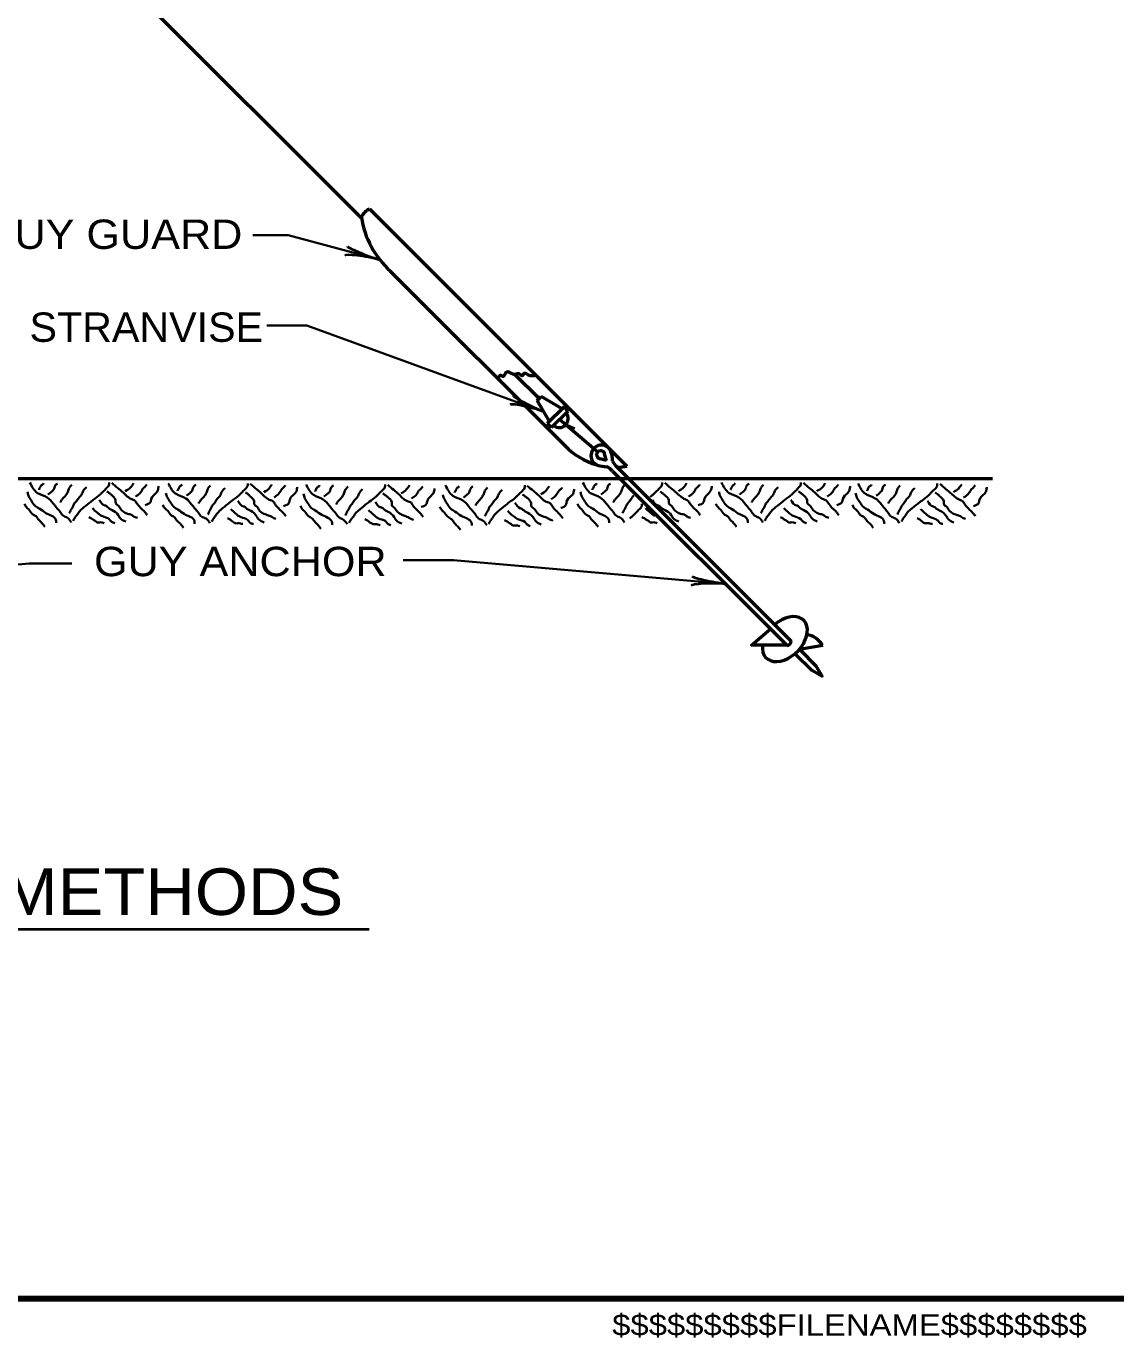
# Model space of a CAD drawing. Extents: x -34 to 821, y -14 to 530.
# Drawn here: x 481.5 to 593.8, y -6.2 to 128.9 of the extents above; entities that cross this region are included whole.
import ezdxf
from ezdxf.enums import TextEntityAlignment as Align

# ---------------------------------------------------------------- set-up
doc = ezdxf.new("R2010")
doc.units = 0
doc.header["$LTSCALE"] = 1.2
doc.layers.add('1', color=7, linetype='Continuous', lineweight=53)

msp = doc.modelspace()

# ---------------------------------------------------------------- linework, layer by layer
at = {"layer": '1'}
for p, q in [((462.551, 162.594), (516.047, 109.122)), ((516.887, 110.082), (543.407, 83.562)), ((519.023, 103.674), (536.999, 85.698)), ((531.791, 93.09), (534.359, 90.546)), ((534.143, 90.33), (534.575, 90.738)), ((536.711, 89.466), (534.575, 90.738)), ((535.415, 88.17), (534.143, 90.33)), ((536.927, 89.682), (535.199, 87.978)), ((537.335, 89.25), (535.631, 87.546)), ((537.335, 89.25), (536.927, 89.682)), ((535.631, 87.546), (535.199, 87.978)), ((540.407, 85.026), (536.447, 88.362)), ((537.095, 87.834), (537.983, 87.402)), ((541.295, 84.138), (540.599, 84.33)), ((541.295, 84.138), (541.103, 84.834)), ((542.351, 83.514), (560.327, 65.538)), ((355.079, 82.29), (581.063, 82.29)), ((561.191, 64.698), (563.567, 65.106)), ((561.191, 64.698), (562.895, 62.97))]:
    msp.add_line(p, q, dxfattribs=at)
at = {"layer": '1', "lineweight": 35}
for p, q in [((508.511, 107.37), (504.863, 107.37)), ((517.847, 104.85), (508.511, 107.37)), ((510.407, 98.058), (506.303, 98.058)), ((534.815, 89.178), (510.407, 98.058)), ((481.823, 73.53), (461.831, 71.778)), ((481.823, 73.53), (486.215, 73.53)), ((525.527, 73.89), (520.343, 73.89)), ((525.527, 73.89), (553.535, 71.442))]:
    msp.add_line(p, q, dxfattribs=at)
at = {"layer": '1', "lineweight": 40}
msp.add_line((426.765, 35.847), (516.827, 35.847), dxfattribs=at)
at = {"layer": '1', "lineweight": 158}
msp.add_line((814.88, -2.224), (23.28, -2.224), dxfattribs=at)
at = {"layer": '1'}
for points in [[(541.919, 83.058), (559.871, 65.106), (556.247, 65.106), (558.167, 66.786)], [(560.735, 64.242), (562.439, 62.538), (563.519, 61.914), (562.895, 62.97)]]:
    msp.add_lwpolyline(points, dxfattribs=at)
for centre, radius, start, end in [((517.718, 108.403), 1.872, 116.15616, 153.84384), ((525.291, 110.626), 9.358, 188.58388, 228.01714), ((536.43, 88.454), 0.911, 230.20411, 39.79589), ((542.156, 90.508), 7.05, 222.90975, 254.56822), ((540.763, 84.67), 1.073, 22.37581, 247.62419), ((540.7, 84.731), 0.423, 13.9871, 256.0129), ((539.132, 84.15), 2.783, 358.69833, 19.49446), ((543.511, 84.865), 1.777, 205.99574, 229.75423), ((541.398, 86.842), 3.332, 251.74116, 268.96028), ((540.559, 81.914), 1.777, 40.24577, 64.00426), ((542.156, 90.508), 7.05, 272.0576, 280.22035), ((561.432, 63.756), 2.526, 32.48706, 78.42981), ((559.86, 65.564), 0.464, 272.04039, 357.95961)]:
    msp.add_arc(centre, radius, start, end, dxfattribs=at)
at = {"layer": '1', "lineweight": 40}
for centre, major_axis, ratio, start_param, end_param in [((516.604, 105.456), (1.997, -0.755), 0.07063, 3.1407148, 5.41811), ((516.486, 104.877), (2.135, -0.377), 0.122415, 0.8963533, 3.1415927), ((533.634, 89.885), (-1.924, 0.926), 0.07063, 6.2823074, 8.5597026), ((533.634, 89.885), (-1.924, 0.926), 0.07063, 6.2823074, 8.5597026), ((533.465, 89.318), (2.094, -0.561), 0.122415, 0.8963533, 3.1415927), ((533.465, 89.318), (2.094, -0.561), 0.122415, 0.8963533, 3.1415927), ((552.207, 71.815), (2.098, -0.397), 0.07063, 3.1407148, 5.41811), ((552.191, 71.224), (2.168, 0), 0.122415, 0.8963533, 3.1415927)]:
    msp.add_ellipse(centre, major_axis=major_axis, ratio=ratio, start_param=start_param, end_param=end_param, dxfattribs=at)
at = {"layer": '1'}
msp.add_ellipse((559.673, 65.751), major_axis=(-1.934, -1.934), ratio=0.663245, start_param=5.5824837, end_param=10.8796755, dxfattribs=at)
msp.add_spline([(530.159, 92.562), (530.423, 92.946), (530.591, 92.826), (530.903, 93.138), (531.095, 93.306), (531.479, 93.138), (532.007, 93.066), (532.247, 93.114), (532.631, 92.898), (532.823, 93.138), (533.231, 92.994), (533.591, 92.898), (533.999, 92.97)], degree=3, dxfattribs=at)
at = {"layer": '1', "lineweight": 35}
for points in [[(481.895, 81.882), (482.663, 80.802), (483.671, 80.346), (484.295, 79.722), (484.607, 79.338), (484.991, 78.858), (485.303, 78.474), (485.759, 78.258), (486.143, 77.778)], [(483.287, 81.81), (483.167, 81.642), (483.119, 81.642), (483.047, 81.57), (482.855, 81.21), (482.831, 81.138)], [(484.727, 81.762), (484.487, 81.57), (484.415, 81.378), (484.319, 81.138), (484.175, 80.994), (484.103, 80.922), (483.743, 80.634)], [(486.215, 81.642), (485.999, 81.402), (485.831, 81.018), (485.639, 80.634), (485.231, 80.178), (485.063, 79.938), (484.991, 79.818)], [(487.727, 81.402), (487.391, 81.018), (487.199, 80.61), (486.887, 80.25), (486.647, 79.914), (486.407, 79.626), (486.311, 79.362), (486.143, 79.098), (485.951, 78.714)], [(490.055, 81.882), (490.055, 81.738), (489.983, 81.498), (489.815, 81.354), (489.671, 81.186), (489.359, 80.874), (489.119, 80.658), (488.423, 80.106), (488.039, 79.794), (487.271, 79.17), (486.959, 78.858), (486.815, 78.642), (486.575, 78.33), (486.335, 77.946)], [(490.319, 81.858), (490.943, 81.306), (491.495, 80.85), (492.407, 80.154), (492.647, 80.058), (492.887, 79.77), (493.271, 79.29), (493.727, 78.834), (493.967, 78.522)], [(491.711, 80.994), (492.263, 81.378), (492.383, 81.522), (492.575, 81.81)], [(492.767, 80.442), (493.199, 80.754), (493.463, 81.138), (493.535, 81.258), (493.703, 81.402), (493.919, 81.69)], [(493.775, 79.554), (494.303, 79.866), (494.399, 80.202), (494.903, 80.826), (495.047, 81.018), (495.119, 81.33), (495.167, 81.498)], [(496.151, 81.786), (496.943, 80.706), (497.951, 80.25), (498.551, 79.626), (498.863, 79.242), (499.247, 78.762), (499.559, 78.378), (500.039, 78.162), (500.423, 77.682)], [(497.567, 81.69), (497.447, 81.546), (497.399, 81.546), (497.327, 81.474), (497.135, 81.114), (497.087, 81.042)], [(498.983, 81.666), (498.767, 81.474), (498.671, 81.282), (498.599, 81.042), (498.455, 80.898), (498.359, 80.802), (498.023, 80.538)], [(500.495, 81.546), (500.255, 81.306), (500.111, 80.922), (499.919, 80.538), (499.487, 80.082), (499.343, 79.842), (499.247, 79.722)], [(502.007, 81.306), (501.647, 80.922), (501.455, 80.49), (501.143, 80.154), (500.927, 79.794), (500.687, 79.53), (500.567, 79.266), (500.423, 79.002), (500.231, 78.594)], [(504.335, 81.786), (504.335, 81.642), (504.239, 81.402), (504.095, 81.234), (503.951, 81.09), (503.639, 80.778), (503.399, 80.538), (502.703, 80.01), (502.319, 79.698), (501.551, 79.074), (501.239, 78.762), (501.071, 78.546), (500.855, 78.234), (500.615, 77.85)], [(504.599, 81.738), (505.223, 81.21), (505.751, 80.754), (506.687, 80.058), (506.927, 79.962), (507.143, 79.65), (507.527, 79.194), (508.007, 78.738), (508.247, 78.426)], [(505.991, 80.898), (506.543, 81.282), (506.639, 81.426), (506.831, 81.69)], [(507.047, 80.346), (507.455, 80.658), (507.743, 81.042), (507.815, 81.162), (507.959, 81.306), (508.199, 81.594)], [(508.031, 79.458), (508.583, 79.77), (508.655, 80.106), (509.159, 80.73), (509.327, 80.922), (509.399, 81.234), (509.423, 81.402)], [(510.335, 81.69), (511.103, 80.61), (512.111, 80.13), (512.735, 79.53), (513.047, 79.122), (513.431, 78.666), (513.743, 78.282), (514.199, 78.042), (514.583, 77.586)], [(511.727, 81.594), (511.607, 81.45), (511.583, 81.45), (511.487, 81.378), (511.295, 81.018), (511.271, 80.946)], [(513.167, 81.57), (512.927, 81.378), (512.855, 81.186), (512.783, 80.946), (512.615, 80.778), (512.543, 80.706), (512.183, 80.442)], [(514.679, 81.45), (514.439, 81.21), (514.271, 80.826), (514.079, 80.442), (513.671, 79.986), (513.503, 79.746), (513.431, 79.626)], [(516.167, 81.21), (515.831, 80.826), (515.639, 80.394), (515.327, 80.058), (515.087, 79.698), (514.871, 79.434), (514.751, 79.17), (514.583, 78.882), (514.391, 78.498)], [(518.495, 81.69), (518.495, 81.522), (518.423, 81.306), (518.255, 81.138), (518.111, 80.994), (517.799, 80.682), (517.559, 80.442), (516.863, 79.914), (516.479, 79.602), (515.711, 78.978), (515.399, 78.666), (515.255, 78.426), (515.015, 78.138), (514.775, 77.73)], [(518.759, 81.642), (519.383, 81.114), (519.935, 80.634), (520.847, 79.938), (521.087, 79.866), (521.327, 79.554), (521.711, 79.098), (522.167, 78.642), (522.407, 78.33)], [(520.151, 80.778), (520.703, 81.186), (520.823, 81.33), (521.015, 81.594)], [(521.207, 80.25), (521.639, 80.562), (521.903, 80.946), (521.975, 81.066), (522.143, 81.21), (522.359, 81.474)], [(522.215, 79.362), (522.743, 79.674), (522.839, 80.01), (523.343, 80.634), (523.487, 80.826), (523.559, 81.138), (523.607, 81.282)], [(524.711, 81.594), (525.479, 80.514), (526.487, 80.034), (527.111, 79.41), (527.423, 79.026), (527.807, 78.57), (528.119, 78.186), (528.575, 77.946), (528.959, 77.49)], [(526.103, 81.498), (525.983, 81.354), (525.935, 81.354), (525.863, 81.258), (525.671, 80.922), (525.623, 80.85)], [(527.519, 81.474), (527.303, 81.258), (527.231, 81.066), (527.135, 80.85), (526.991, 80.682), (526.919, 80.61), (526.559, 80.346)], [(529.031, 81.354), (528.815, 81.114), (528.647, 80.73), (528.455, 80.346), (528.023, 79.866), (527.879, 79.65), (527.807, 79.53)], [(530.543, 81.114), (530.207, 80.73), (530.015, 80.298), (529.703, 79.962), (529.463, 79.602), (529.223, 79.338), (529.127, 79.074), (528.959, 78.786), (528.767, 78.402)], [(532.871, 81.594), (532.871, 81.426), (532.799, 81.21), (532.631, 81.042), (532.487, 80.898), (532.175, 80.586), (531.935, 80.346), (531.239, 79.818), (530.855, 79.506), (530.087, 78.882), (529.775, 78.57), (529.607, 78.33), (529.391, 78.018), (529.151, 77.634)], [(533.135, 81.546), (533.759, 81.018), (534.311, 80.538), (535.223, 79.842), (535.463, 79.77), (535.703, 79.458), (536.087, 79.002), (536.543, 78.522), (536.783, 78.21)], [(534.527, 80.682), (535.079, 81.066), (535.199, 81.234), (535.391, 81.498)], [(535.583, 80.154), (536.015, 80.466), (536.279, 80.85), (536.351, 80.97), (536.495, 81.114), (536.735, 81.378)], [(536.591, 79.266), (537.119, 79.578), (537.191, 79.914), (537.695, 80.538), (537.863, 80.73), (537.935, 81.042), (537.983, 81.186)], [(538.871, 81.882), (539.639, 80.802), (540.647, 80.346), (541.271, 79.722), (541.583, 79.338), (541.967, 78.858), (542.279, 78.474), (542.735, 78.258), (543.143, 77.778)], [(540.263, 81.81), (540.143, 81.642), (540.119, 81.642), (540.047, 81.57), (539.855, 81.21), (539.807, 81.138)], [(541.703, 81.762), (541.463, 81.57), (541.391, 81.378), (541.319, 81.138), (541.151, 80.994), (541.079, 80.922), (540.743, 80.634)], [(543.215, 81.642), (542.975, 81.402), (542.831, 81.018), (542.639, 80.634), (542.207, 80.178), (542.039, 79.938), (541.967, 79.818)], [(547.031, 81.882), (547.031, 81.738), (546.959, 81.498), (546.815, 81.354), (546.647, 81.186), (546.335, 80.874), (546.119, 80.658), (545.807, 80.418)], [(547.319, 81.858), (547.919, 81.306), (548.471, 80.85), (549.407, 80.154), (549.623, 80.058), (549.863, 79.77), (550.247, 79.29), (550.727, 78.834), (550.943, 78.522)], [(548.711, 80.994), (549.239, 81.378), (549.359, 81.522), (549.551, 81.81)], [(549.743, 80.442), (550.175, 80.754), (550.439, 81.138), (550.511, 81.258), (550.679, 81.402), (550.919, 81.69)], [(550.751, 79.554), (551.303, 79.866), (551.375, 80.202), (551.879, 80.826), (552.023, 81.018), (552.119, 81.33), (552.143, 81.498)], [(553.151, 81.882), (553.919, 80.802), (554.927, 80.346), (555.551, 79.722), (555.863, 79.338), (556.247, 78.858), (556.559, 78.474), (557.015, 78.258), (557.399, 77.778)], [(554.543, 81.81), (554.423, 81.642), (554.375, 81.642), (554.303, 81.57), (554.111, 81.21), (554.087, 81.138)], [(555.983, 81.762), (555.743, 81.57), (555.671, 81.378), (555.575, 81.138), (555.431, 80.994), (555.359, 80.922), (554.999, 80.634)], [(557.471, 81.642), (557.255, 81.402), (557.087, 81.018), (556.895, 80.634), (556.463, 80.178), (556.319, 79.938), (556.247, 79.818)], [(558.983, 81.402), (558.647, 81.018), (558.455, 80.61), (558.143, 80.25), (557.903, 79.914), (557.663, 79.626), (557.567, 79.362), (557.399, 79.098), (557.207, 78.714)], [(561.311, 81.882), (561.311, 81.738), (561.239, 81.498), (561.071, 81.354), (560.927, 81.186), (560.615, 80.874), (560.375, 80.658), (559.679, 80.106), (559.295, 79.794), (558.527, 79.17), (558.215, 78.858), (558.071, 78.642), (557.831, 78.33), (557.591, 77.946)], [(561.575, 81.858), (562.199, 81.306), (562.751, 80.85), (563.663, 80.154), (563.903, 80.058), (564.143, 79.77), (564.527, 79.29), (564.983, 78.834), (565.223, 78.522)], [(562.967, 80.994), (563.519, 81.378), (563.639, 81.522), (563.831, 81.81)], [(564.023, 80.442), (564.455, 80.754), (564.719, 81.138), (564.791, 81.258), (564.959, 81.402), (565.175, 81.69)], [(565.031, 79.554), (565.559, 79.866), (565.655, 80.202), (566.159, 80.826), (566.303, 81.018), (566.375, 81.33), (566.423, 81.498)], [(567.215, 81.786), (567.983, 80.706), (568.991, 80.25), (569.615, 79.626), (569.927, 79.242), (570.311, 78.762), (570.623, 78.378), (571.079, 78.162), (571.463, 77.682)], [(568.607, 81.69), (568.487, 81.546), (568.463, 81.546), (568.367, 81.474), (568.175, 81.114), (568.151, 81.042)], [(570.047, 81.666), (569.807, 81.474), (569.735, 81.282), (569.663, 81.042), (569.495, 80.898), (569.423, 80.802), (569.087, 80.538)], [(571.559, 81.546), (571.319, 81.306), (571.175, 80.922), (570.983, 80.538), (570.551, 80.082), (570.383, 79.842), (570.311, 79.722)], [(573.071, 81.306), (572.711, 80.922), (572.519, 80.49), (572.207, 80.154), (571.967, 79.794), (571.751, 79.53), (571.631, 79.266), (571.463, 79.002), (571.271, 78.594)], [(575.375, 81.786), (575.375, 81.642), (575.303, 81.402), (575.159, 81.234), (574.991, 81.09), (574.679, 80.778), (574.463, 80.538), (573.767, 80.01), (573.359, 79.698), (572.591, 79.074), (572.279, 78.762), (572.135, 78.546), (571.895, 78.234), (571.679, 77.85)], [(575.663, 81.738), (576.263, 81.21), (576.815, 80.754), (577.751, 80.058), (577.967, 79.962), (578.207, 79.65), (578.591, 79.194), (579.047, 78.738), (579.287, 78.426)], [(577.055, 80.898), (577.583, 81.282), (577.703, 81.426), (577.895, 81.69)], [(578.087, 80.346), (578.519, 80.658), (578.783, 81.042), (578.855, 81.162), (579.023, 81.306), (579.263, 81.594)], [(579.095, 79.458), (579.647, 79.77), (579.719, 80.106), (580.223, 80.73), (580.367, 80.922), (580.463, 81.234), (580.487, 81.402)], [(481.631, 80.922), (481.775, 80.442), (482.087, 79.938), (482.471, 79.434), (482.855, 79.218), (483.527, 78.738), (484.559, 78.042), (484.607, 77.73)], [(489.047, 80.106), (489.623, 79.506), (489.743, 79.482), (489.863, 79.362), (490.367, 79.05), (490.991, 78.522), (491.183, 78.21), (491.759, 77.85)], [(489.815, 80.946), (490.055, 80.802), (490.295, 80.61), (490.703, 80.058), (490.751, 79.722), (491.063, 79.434), (491.183, 79.242), (491.951, 78.666), (492.407, 78.522), (492.527, 78.426), (492.959, 78.234)], [(495.887, 80.802), (496.055, 80.346), (496.367, 79.842), (496.751, 79.338), (497.135, 79.098), (497.783, 78.642), (498.839, 77.946), (498.863, 77.634)], [(503.327, 79.986), (503.903, 79.41), (504.023, 79.386), (504.143, 79.266), (504.647, 78.954), (505.247, 78.402), (505.439, 78.114), (506.039, 77.754)], [(504.095, 80.85), (504.335, 80.706), (504.551, 80.49), (504.983, 79.962), (505.031, 79.602), (505.343, 79.338), (505.439, 79.146), (506.231, 78.57), (506.687, 78.402), (506.807, 78.33), (507.239, 78.138)], [(510.071, 80.706), (510.215, 80.25), (510.527, 79.746), (510.911, 79.242), (511.295, 79.002), (511.967, 78.546), (512.999, 77.85), (513.047, 77.538)], [(517.487, 79.89), (518.063, 79.314), (518.183, 79.29), (518.303, 79.17), (518.807, 78.858), (519.431, 78.306), (519.623, 77.994), (520.199, 77.658)], [(518.255, 80.754), (518.495, 80.586), (518.735, 80.394), (519.167, 79.866), (519.191, 79.506), (519.503, 79.242), (519.623, 79.05), (520.391, 78.474), (520.847, 78.306), (520.967, 78.234), (521.399, 78.042)], [(524.423, 80.61), (524.591, 80.154), (524.903, 79.65), (525.287, 79.146), (525.671, 78.906), (526.319, 78.45), (527.375, 77.754), (527.423, 77.442)], [(531.863, 79.794), (532.439, 79.218), (532.559, 79.17), (532.679, 79.074), (533.183, 78.762), (533.807, 78.21), (533.999, 77.898), (534.575, 77.562)], [(532.631, 80.658), (532.871, 80.49), (533.111, 80.298), (533.519, 79.77), (533.567, 79.41), (533.879, 79.146), (533.999, 78.954), (534.767, 78.378), (535.223, 78.21), (535.343, 78.138), (535.775, 77.946)], [(538.607, 80.922), (538.751, 80.442), (539.063, 79.938), (539.447, 79.434), (539.855, 79.218), (540.503, 78.738), (541.535, 78.042), (541.583, 77.73)], [(544.127, 80.538), (543.863, 80.25), (543.647, 79.914), (543.407, 79.626), (543.287, 79.362), (543.143, 79.098), (542.927, 78.714)], [(546.023, 80.106), (546.623, 79.506), (546.719, 79.482), (546.839, 79.362), (547.343, 79.05), (547.967, 78.522), (548.159, 78.21), (548.735, 77.85)], [(546.815, 80.946), (547.031, 80.802), (547.271, 80.61), (547.703, 80.058), (547.727, 79.722), (548.039, 79.434), (548.159, 79.242), (548.927, 78.666), (549.407, 78.522), (549.527, 78.426), (549.935, 78.234)], [(552.887, 80.922), (553.031, 80.442), (553.343, 79.938), (553.727, 79.434), (554.111, 79.218), (554.783, 78.738), (555.815, 78.042), (555.863, 77.73)], [(560.303, 80.106), (560.879, 79.506), (560.999, 79.482), (561.119, 79.362), (561.623, 79.05), (562.247, 78.522), (562.439, 78.21), (563.015, 77.85)], [(561.071, 80.946), (561.311, 80.802), (561.551, 80.61), (561.959, 80.058), (562.007, 79.722), (562.319, 79.434), (562.439, 79.242), (563.207, 78.666), (563.663, 78.522), (563.783, 78.426), (564.215, 78.234)], [(566.951, 80.802), (567.095, 80.346), (567.407, 79.842), (567.791, 79.338), (568.175, 79.098), (568.847, 78.642), (569.879, 77.946), (569.927, 77.634)], [(574.367, 79.986), (574.967, 79.41), (575.063, 79.386), (575.183, 79.266), (575.687, 78.954), (576.311, 78.402), (576.503, 78.114), (577.079, 77.754)], [(575.159, 80.85), (575.375, 80.706), (575.615, 80.49), (576.047, 79.962), (576.071, 79.602), (576.383, 79.338), (576.503, 79.146), (577.271, 78.57), (577.751, 78.402), (577.847, 78.33), (578.279, 78.138)], [(481.319, 79.674), (481.463, 79.41), (481.775, 79.098), (482.159, 78.618), (482.519, 78.402), (482.831, 78.018), (483.119, 77.706), (483.431, 77.322)], [(488.327, 79.242), (488.807, 78.786), (489.023, 78.618), (489.359, 78.402), (490.055, 78.114), (490.295, 77.85), (490.631, 77.706)], [(495.575, 79.578), (495.743, 79.29), (496.055, 79.002), (496.439, 78.522), (496.775, 78.306), (497.087, 77.898), (497.399, 77.61), (497.711, 77.202)], [(502.583, 79.146), (503.087, 78.69), (503.279, 78.522), (503.639, 78.306), (504.335, 78.018), (504.551, 77.754), (504.911, 77.61)], [(509.759, 79.482), (509.903, 79.194), (510.215, 78.882), (510.599, 78.426), (510.959, 78.186), (511.271, 77.802), (511.583, 77.49), (511.871, 77.106)], [(516.767, 79.05), (517.271, 78.594), (517.463, 78.426), (517.799, 78.186), (518.495, 77.922), (518.735, 77.658), (519.071, 77.49)], [(524.135, 79.362), (524.279, 79.098), (524.591, 78.786), (524.975, 78.33), (525.335, 78.09), (525.623, 77.706), (525.935, 77.394), (526.247, 77.01)], [(531.119, 78.954), (531.623, 78.474), (531.815, 78.33), (532.175, 78.09), (532.871, 77.826), (533.111, 77.562), (533.447, 77.394)], [(538.295, 79.674), (538.439, 79.41), (538.751, 79.098), (539.135, 78.618), (539.495, 78.402), (539.807, 78.018), (540.119, 77.706), (540.431, 77.322)], [(544.919, 79.674), (544.919, 79.506), (544.847, 79.29), (544.679, 79.122), (544.535, 78.978), (544.223, 78.666), (543.983, 78.426), (543.695, 78.186)], [(545.303, 79.242), (545.807, 78.786), (545.999, 78.618), (546.263, 78.45)], [(552.575, 79.674), (552.719, 79.41), (553.031, 79.098), (553.415, 78.618), (553.775, 78.402), (554.087, 78.018), (554.375, 77.706), (554.687, 77.322)], [(559.559, 79.242), (560.063, 78.786), (560.255, 78.618), (560.615, 78.402), (561.311, 78.114), (561.551, 77.85), (561.887, 77.706)], [(566.639, 79.578), (566.783, 79.29), (567.095, 79.002), (567.479, 78.522), (567.839, 78.306), (568.151, 77.898), (568.463, 77.61), (568.775, 77.202)], [(573.647, 79.146), (574.151, 78.69), (574.343, 78.522), (574.679, 78.306), (575.375, 78.018), (575.615, 77.754), (575.951, 77.61)], [(487.967, 78.306), (488.231, 78.162), (488.735, 77.826), (488.807, 77.778), (489.047, 77.778), (489.551, 77.706)], [(502.247, 78.21), (502.511, 78.066), (503.015, 77.706), (503.087, 77.682), (503.327, 77.682), (503.831, 77.61)], [(516.407, 78.114), (516.671, 77.97), (517.175, 77.61), (517.271, 77.586), (517.487, 77.586), (517.991, 77.49)], [(530.783, 78.018), (531.047, 77.874), (531.551, 77.514), (531.623, 77.466), (531.863, 77.466), (532.367, 77.394)], [(544.943, 78.306), (545.231, 78.162), (545.735, 77.826), (545.807, 77.778), (546.023, 77.778), (546.527, 77.706)], [(559.223, 78.306), (559.487, 78.162), (559.991, 77.826), (560.063, 77.778), (560.303, 77.778), (560.807, 77.706)], [(573.287, 78.21), (573.575, 78.066), (574.055, 77.706), (574.151, 77.682), (574.367, 77.682), (574.871, 77.61)]]:
    msp.add_spline(points, degree=3, dxfattribs=at)

# ---------------------------------------------------------------- texts
at = {"layer": '1', "width": 1.1}
for s, p in [('GUY GUARD', (490.309, 105.954)), ('GUY ANCHOR', (503.568, 72.234))]:
    msp.add_text(s, height=3.024, dxfattribs=at).set_placement(p, align=Align.CENTER)
at = {"layer": '1'}
for s, height, width, p in [('STRANVISE', 3.024, 1.05, (481.847, 96.378)), ('POLE GUYING METHODS', 4.8, 1.1, (428.261, 37.322)), ('$$$$$$$$$FILENAME$$$$$$$$', 2.2, 1.15, (541.88, -6.024))]:
    msp.add_text(s, height=height, dxfattribs=dict(at, width=width)).set_placement(p)

doc.saveas('drawing.dxf')
